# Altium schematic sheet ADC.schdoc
size 314 x 219 mm
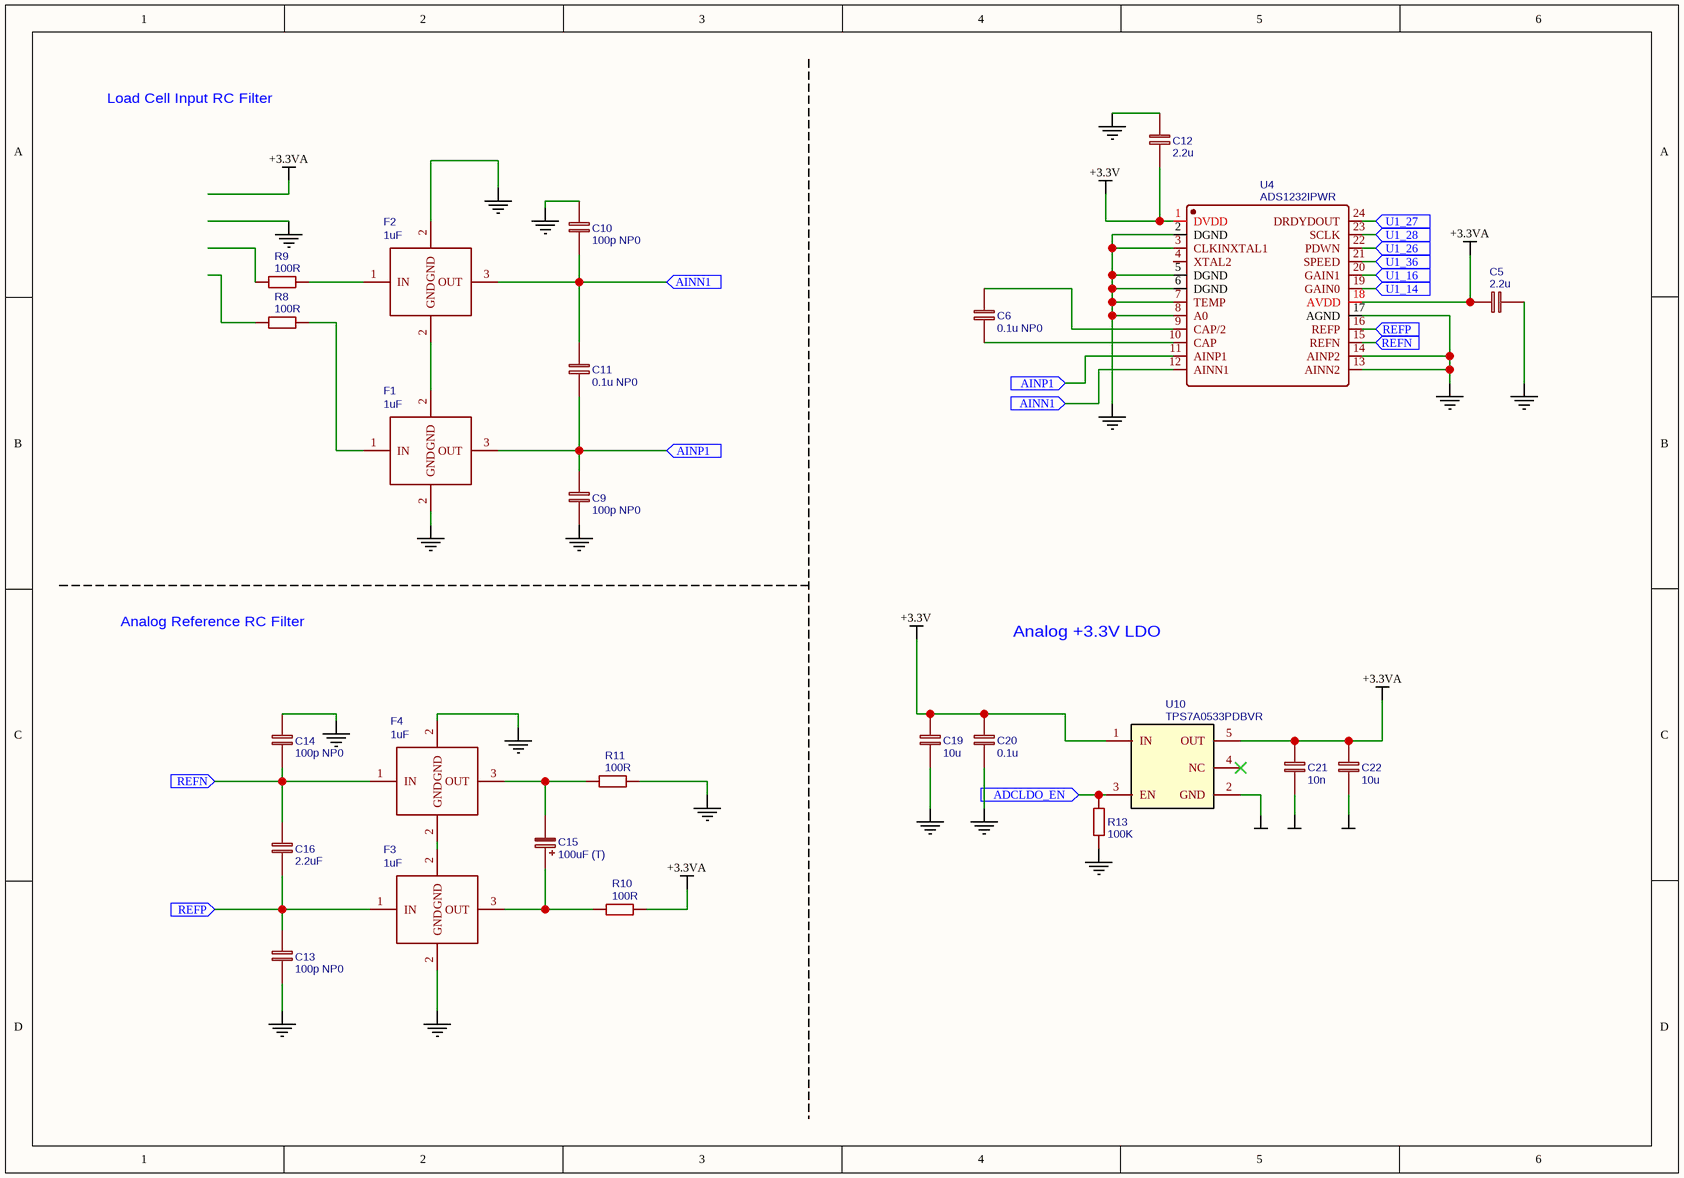
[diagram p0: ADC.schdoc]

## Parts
C5  2.2u  [0805]
C6  0.1u NP0  [1206]
C9  100p NP0  [0805]
C10  100p NP0  [0805]
C11  0.1u NP0  [1206]
C12  2.2u  [0805]
C13  100p NP0  [0805]
C14  100p NP0  [0805]
C15  100uF (T)  [CASE-C_6032]
C16  2.2uF  [0805]
C19  10u  [0805]
C20  0.1u  [0805]
C21  10n  [0805]
C22  10u  [0805]
F1  1uF  [NFM21-0805-4PIN]
F2  1uF  [NFM21-0805-4PIN]
F3  1uF  [NFM21-0805-4PIN]
F4  1uF  [NFM21-0805-4PIN]
R8  100R  [0805]
R9  100R  [0805]
R10  100R  [0805]
R11  100R  [0805]
R13  100K  [0805]
U4  ADS1232IPWR  [TSSOP-24]
U10  TPS7A0533PDBVR  [SOT-23-5]

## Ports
ADCLDO_EN, AINN1, AINP1, REFN, REFP, U1_14, U1_16, U1_26, U1_27, U1_28, U1_36

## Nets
+3.3V: C12.2 C19.1 C20.1 U4.1(DVDD) U10.1(IN)
+3.3VA: C5.1 C21.1 C22.1 U4.18(AVDD) U10.5(OUT)
GND: C5.2 C9.2 C10.1 C12.1 C13.2 C14.1 C19.2 C20.2 C21.2 C22.2 F1.2(GND) F2.2(GND) F3.2(GND) F4.2(GND) U4.2(DGND) U4.3(CLKINXTAL1) U4.5(DGND) U4.6(DGND) U4.7(TEMP) U4.8(A0) U4.13(AINN2) U4.14(AINP2) U4.17(AGND) U10.2(GND)
ADCLDO_EN: U10.3(EN) ; port ADCLDO_EN
AINN1: C10.2 C11.1 F2.3(OUT) U4.12(AINN1) ; port AINN1
AINP1: C9.1 C11.2 F1.3(OUT) U4.11(AINP1) ; port AINP1
REFN: C14.2 C16.1 F4.1(IN) U4.15(REFN) ; port REFN
REFP: C13.1 C16.2 F3.1(IN) U4.16(REFP) ; port REFP
U1_14: U4.19(GAIN0) ; port U1_14
U1_16: U4.20(GAIN1) ; port U1_16
U1_26: U4.22(PDWN) ; port U1_26
U1_27: U4.24(DRDYDOUT) ; port U1_27
U1_28: U4.23(SCLK) ; port U1_28
U1_36: U4.21(SPEED) ; port U1_36
NetC6_1: C6.1 U4.9(CAP/2)
NetC6_2: C6.2 U4.10(CAP)
NetC15_1: C15.1 F3.3(OUT)
NetC15_2: C15.2 F4.3(OUT)
NetF1_2: F1.2(GND) F2.2(GND)
NetF3_2: F3.2(GND) F4.2(GND)

Not connected (* = marked no-connect by the designer): F1 1(IN); F2 1(IN); R8 1 2; R9 1 2; R10 1 2; R11 1 2; R13 1 2; U4 4(XTAL2); U10 4(NC)*

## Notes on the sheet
- Load Cell Input RC Filter
- Analog Reference RC Filter
- Analog +3.3V LDO
- Labels drawn without touching a wire or pin: GND

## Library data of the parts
C5 C12 = 2.2u: nameAlias: Value(F)
C6 C11 = 0.1u NP0: nameAlias: Value(F)
C9 C10 C13 C14 = 100p NP0: nameAlias: Value(F)
C15 = 100uF (T): nameAlias: Value(F); Contributor: EasyEDA
C16 = 2.2uF: nameAlias: Value(F)
C19 C22 = 10u: nameAlias: Value(F)
C20 = 0.1u: nameAlias: Value(F)
C21 = 10n: nameAlias: Value(F)
F1-F4 = 1uF: BOM_Manufacturer: MuRata; BOM_Manufacturer Part: NFM21PC105B1C3D; nameAlias: Value(H); Value: 1.0μF(105)
R8-R11 = 100R: nameAlias: Value(Ω)
R13 = 100K: nameAlias: Value(Ω)
U4 = ADS1232IPWR: BOM_Manufacturer: TI; Contributor: LCSC
U10 = TPS7A0533PDBVR: BOM_Manufacturer: TI; Contributor: blocked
